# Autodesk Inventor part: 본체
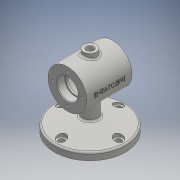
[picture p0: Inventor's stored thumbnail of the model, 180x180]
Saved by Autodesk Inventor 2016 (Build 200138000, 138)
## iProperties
Created: 2018-12
Part Number: 본체
Material: 일반
Document SubType Name: Modeling
Designer: USER
Density: 1 g/cm^3
Appearance: 기본값
Author: USER
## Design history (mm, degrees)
sketch "스케치1"
  geometry: C1 r 30 at (0, 75); 1 further point
  constraints: 1 centre point, 1 vertical alignment
  dimensions: "d0" = 60 diameter of C1; "d1" = 75 distance of point (0, 0) C1.centre
extrude "돌출1" new body sketch "스케치1" distance "d2" = 70; taper "d3" = 0 deg
sketch "스케치2"
  geometry: L1 (0, 105)-(0, 45) reference; L2 (0, 75)-(70, 75); L3 (70, 45)-(70, 105) reference; L4 (0, 75)-(0, 91); L5 (0, 91)-(12, 91); L6 (12, 91)-(12, 89); L7 (12, 89)-(15, 89); L8 (15, 89)-(15, 100); L9 (15, 100)-(55, 100); L10 (55, 100)-(55, 89); L11 (55, 89)-(58, 89); L12 (58, 89)-(58, 91); L13 (58, 91)-(70, 91); L14 (70, 91)-(70, 75); 1 further point
  constraints: 24 end point, 6 perpendicular, 2 midpoint, 2 point on line, 1 collinear, 1 parallel, 1 vertical
  dimensions: "d4" = 16 distance of L2.start L4.end; "d5" = 12 distance of L4.end L5.end; "d6" = 2 distance of L5.end L6.end; "d7" = 3 distance of L6.end L7.end; "d8" = 11 distance of L7.end L8.end; "d9" = 40 distance of L8.end L9.end; "d10" = 11 distance of L9.end L10.end; "d11" = 3 distance of L10.end L11.end; "d12" = 2 distance of L11.end L12.end; "d13" = 12 distance of L12.end L13.end
revolve "회전1" sketch "스케치2" stored, may be unused: angle "d14" = 90 deg
node "작업 평면1"
sketch "스케치3"
  geometry: C1 r 10 at (0, 35); 1 further point
  constraints: 1 centre point, 1 vertical alignment
  dimensions: "d16" = 20 diameter of C1; "d17" = 35 distance of point (0, 0) C1.centre
extrude "돌출2" join sketch "스케치3" stored distance "d18" = 70; taper "d19" = 0 deg
sketch "스케치4"
  geometry: C1 r 10 at (0, 0) reference; C2 r 5 at (0, 0); 1 further point
  constraints: 1 centre point, 1 coincident
  dimensions: "d20" = 10 diameter of C2
extrude "돌출3" cut sketch "스케치4" stored distance "d21" = 70; taper "d22" = 0 deg; dims "d4" = 16, "d5" = 12, "d6" = 2, "d7" = 3, "d8" = 11, "d9" = 40, "d10" = 11, "d11" = 3, "d12" = 2, "d13" = 12
sketch "스케치5"
  geometry: C1 r 16 at (0, 0) reference; C2 r 30 at (0, 0) reference; 2 further points
  constraints: 1 vertical alignment
  dimensions: "d23" = 23 distance of point (0, 23) C1.centre
hole "구멍1" sketch "스케치5" at (0, 23) diameter "d24" = 3.242; stored, may be unused: countersink angle "d28" = 90 deg, drill point angle "d30" = 118 deg; dims "d25" = 8, "d26" = 4, "d27" = 2, "d29" = 10
node "작업 평면2"
sketch "스케치6"
  geometry: L1 (30, 70)-(-30, 70) reference; L2 (-25, 15)-(25, 15) reference; L3 (-25, 55)-(25, 55) reference; L4 (-30, 0)-(30, 0) reference; L5 (30, 70)-(-30, 70) reference; C1 r 55 at (0, 35); 4 further points
  constraints: 1 centre point, 1 coincident, 1 horizontal alignment, 2 other
  dimensions: "d35" = 110 diameter of C1
extrude "돌출4" join sketch "스케치6" distance "d36" = 11; taper "d37" = 0 deg
sketch "스케치7"
  geometry: C1 r 55 at (0, 0) reference; C2 r 12 at (0, 0); 1 further point
  constraints: 1 centre point, 1 coincident
  dimensions: "d38" = 24 diameter of C2
extrude "돌출5" join sketch "스케치7" stored distance "d39" = 11; taper "d40" = 0 deg
sketch "스케치8"
  geometry: L1 (-20, 0)-(90, 0) reference; L2 (35, 11)-(35, 25.737); L3 (90, 0)-(90, 11) reference; L4 (90, 11)-(35, 25.737); L5 (90, 11)-(35, 11); L6 (90, 11)-(-20, 11) reference; 1 further point
  constraints: 6 end point, 2 midpoint, 1 vertical
  dimensions: "d41" = 75 deg angle of L4 L3
revolve "회전2" sketch "스케치8" stored, may be unused: angle "d42" = 90 deg
sketch "스케치9"
  geometry: C1 r 55 at (0, 0) reference; C2 r 12 at (0, 0) reference; C3 r 4.5 at (0, -44); 1 further point
  constraints: 1 centre point, 1 vertical alignment
  dimensions: "d43" = 9 diameter of C3; "d44" = 44 distance of C3.centre C1.centre
extrude "돌출6" cut sketch "스케치9" distance "d45" = 10; taper "d46" = 0 deg
sketch "스케치10"
  geometry: C1 r 4.5 at (0, 0) reference; C2 r 7 at (0, 0); 1 further point
  constraints: 1 centre point, 1 coincident
  dimensions: "d47" = 14 diameter of C2
extrude "돌출7" cut sketch "스케치10" stored distance "d48" = 10; taper "d49" = 0 deg
node "작업 평면3"
sketch "스케치11" dims "d2" = 70, "d3" = 0
  geometry: L1 (0, 30)-(0, -30) reference; L2 (0, 30)-(70, 30) reference; 2 further points
  constraints: 1 other
  dimensions: "d53" = 35 distance from line of L1 point (35, 0); "d54" = 30 distance from line of L2 point (35, 0)
feature "엠보싱1" sketch "스케치11" dims "d2" = 70, "d55" = 0.5, "d56" = 0
fillet "모깎기1" dims "d57" = 3
chamfer "모따기1" distance "d58" = 1; stored, may be unused: second distance "d59" = 2, angle "d60" = 45 deg
fillet "모깎기2" dims "d61" = 3
fillet "모깎기3" dims "d62" = 0.3
chamfer "모따기2" distance "d63" = 1; stored, may be unused: second distance "d64" = 2, angle "d65" = 45 deg
node "솔리드1"
pattern_circular "원형 패턴1" dims angle "d32" = 360 deg
mirror "대칭1"
pattern_circular "원형 패턴2" dims angle "d51" = 360 deg
node "투영된 루프1"
node "투영된 루프2"
node "투영된 루프3"
node "투영된 루프4"
node "투영된 루프5"
node "투영된 루프6"
node "투영된 루프7"
other parameters: "d15" = 112, "d34" = -35
